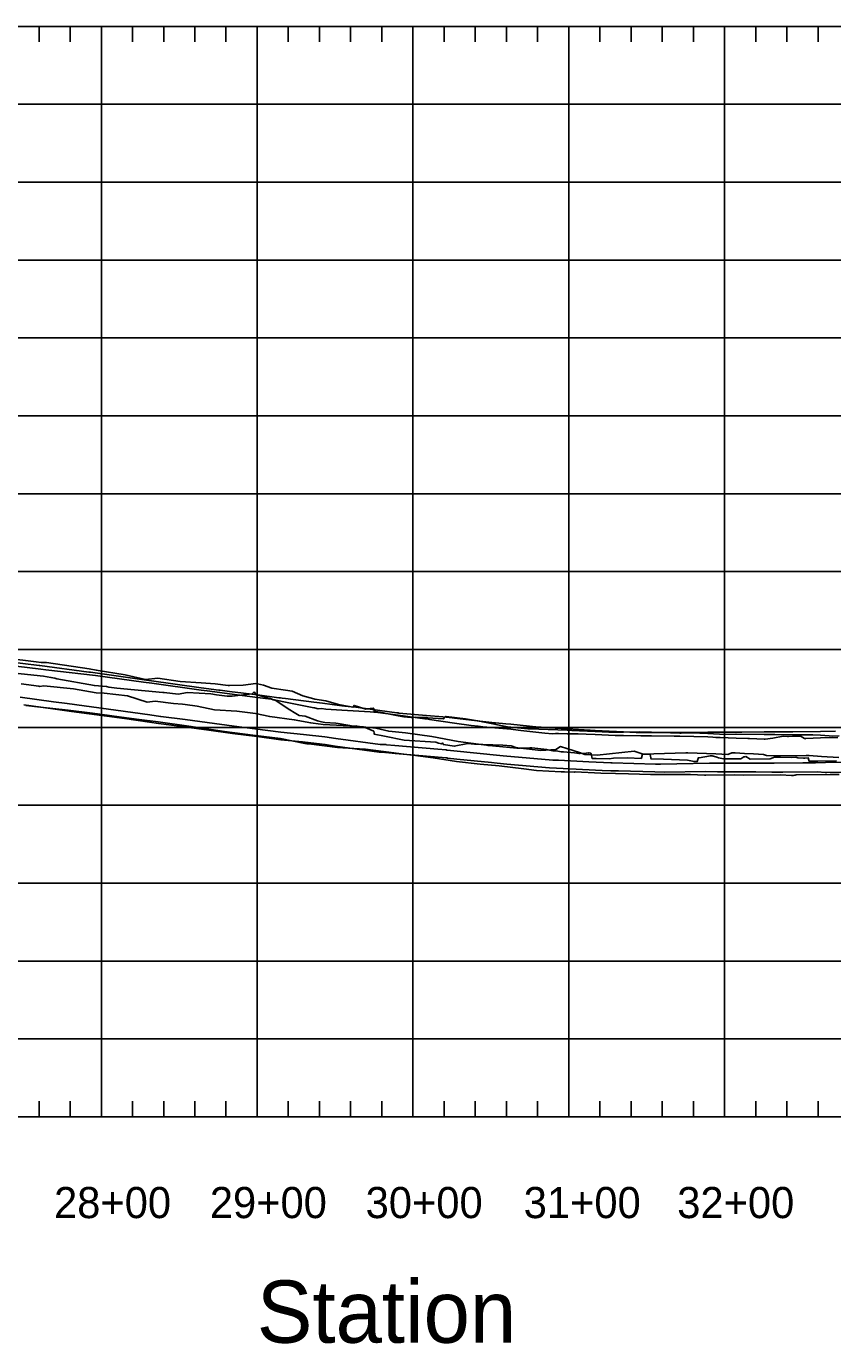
# Model space of a CAD drawing. Extents: x 704797 to 712284, y 374940 to 376945.
# Drawn here: x 709886 to 710403, y 375080 to 375925 of the extents above; entities that cross this region are included whole.
import ezdxf

# ---------------------------------------------------------------- set-up
doc = ezdxf.new("R2010")
doc.units = 0
for name, color, linetype in [('1', 7, 'Continuous'), ('10', 7, 'Continuous'), ('12', 7, 'Continuous'), ('13', 7, 'Continuous'), ('61', 7, 'Continuous'), ('63', 7, 'Continuous'), ('Existing', 7, 'Continuous')]:
    doc.layers.add(name, color=color, linetype=linetype)

msp = doc.modelspace()

# ---------------------------------------------------------------- linework, layer by layer
at = {"layer": '10'}
for points in [[(709874.16, 375510.77), (709896.6, 375508.33), (709901.33, 375507.58), (709903.88, 375507.11), (709905.03, 375506.66), (709929.22, 375502.35), (709936.92, 375501.68), (709938.59, 375501.37), (709943.57, 375500.56), (709973.07, 375497.79), (709973.91, 375497.97), (709983.05, 375496.9), (709988.96, 375497.86), (710003.85, 375496.96), (710007.55, 375496.38), (710014.44, 375495.56), (710017.75, 375495.62), (710030.51, 375497.11), (710031.58, 375498.13), (710031.88, 375498.04), (710033.05, 375496.4), (710042.27, 375494.03), (710043.98, 375493.21), (710045.71, 375492.68), (710053.54, 375487.38), (710058.53, 375484.49), (710060.7, 375483.2), (710064.53, 375482.76), (710072.32, 375479.69), (710074.96, 375479.06), (710077.22, 375478.54), (710084.29, 375478.21), (710085.63, 375477.99), (710096.72, 375476), (710096.96, 375476.45), (710099.86, 375475.54), (710101.93, 375475.8), (710108.48, 375473.03), (710108.73, 375471.73), (710108.84, 375471.09), (710115.47, 375469.77), (710128.15, 375467.26), (710148.28, 375465.93), (710150.14, 375465.42), (710151.19, 375465.11), (710152.13, 375464.82), (710152.17, 375464.81), (710152.19, 375464.8), (710152.44, 375465.2), (710152.63, 375465.48), (710153.07, 375464.65), (710153.23, 375464.48), (710160.24, 375463.33), (710168.93, 375465.17), (710173.26, 375464.68), (710178.44, 375464.42), (710191.28, 375464.14), (710196.68, 375463.55), (710200.34, 375462.34), (710200.95, 375462.27), (710215.7, 375460.59), (710225.37, 375461.34), (710228.32, 375463.16), (710240.54, 375459.32), (710243.97, 375457.99), (710252.02, 375457.64), (710275.68, 375460.31), (710275.75, 375460.31), (710281.54, 375458.28), (710308.82, 375459.2), (710309.49, 375459.18), (710310.05, 375459.15), (710328.09, 375458.41), (710335.69, 375458.07), (710338.46, 375459.16), (710340.4, 375459.07), (710346.55, 375458.77), (710352.36, 375458.45), (710358.7, 375458.06), (710360.67, 375457.53), (710366.75, 375457.18), (710369.64, 375457.29), (710386.12, 375457.39), (710388.07, 375457.4), (710395.99, 375456.88), (710407.07, 375456.25)], [(710405.48, 375454.11), (710393.53, 375453.9), (710387.88, 375453.9), (710387.78, 375454.52), (710387.39, 375455.88), (710385.27, 375455.82), (710384.33, 375455.8), (710380.67, 375455.94), (710379.41, 375456.35), (710376.94, 375456.18), (710369.27, 375456.28), (710365.85, 375456.3), (710362.98, 375455.38), (710350.07, 375455.14), (710347.39, 375456.69), (710346.72, 375456.68), (710346.14, 375456.48), (710344.2, 375455.3), (710342.88, 375455.32), (710339.01, 375455.33), (710333.06, 375455.23), (710329.76, 375455.99), (710328.76, 375456.26), (710326.63, 375456.91), (710326.31, 375456.99), (710325.65, 375457.15), (710325.06, 375457.24), (710324.57, 375457.24), (710320.99, 375456.54), (710317.49, 375455.99), (710316.83, 375455.94), (710316.71, 375455.54), (710316.21, 375453.57), (710314.08, 375453.65), (710309.92, 375454.39), (710294.54, 375455.13), (710286.53, 375455.26), (710286.37, 375455.58), (710286.3, 375456.03), (710285.88, 375458.04), (710284.62, 375458.22), (710283.8, 375458.33), (710282.8, 375458.38), (710280.92, 375458.26), (710280.44, 375456.01), (710280.36, 375455.7), (710280.29, 375455.56), (710271.24, 375455.93), (710262.47, 375455.76), (710259.7, 375455.36), (710251.18, 375455.5), (710248.91, 375455.53), (710248.7, 375455.55), (710248.47, 375456.63), (710248.02, 375458.27), (710247.81, 375458.89), (710247.59, 375458.96), (710246.88, 375459.06), (710246.59, 375459.04), (710246.1, 375459.03), (710245.28, 375459.04), (710245.15, 375459.03), (710241.07, 375458.63), (710240.06, 375458.82), (710238.78, 375459.02), (710237.3, 375459.18), (710230.42, 375459.76), (710228.74, 375459.86), (710225.64, 375460.36), (710223.43, 375460.49), (710221.28, 375460.92), (710219.71, 375461.28), (710209.95, 375462.33), (710209.27, 375462.4), (710209.11, 375462.41), (710208.95, 375462.43), (710208.8, 375462.44), (710202.45, 375462.07), (710201.93, 375462.09), (710201.44, 375462.1), (710200.99, 375462.11), (710200.6, 375462.11), (710200.28, 375462.1), (710182.36, 375463.89), (710181.65, 375463.92), (710181, 375463.96), (710175.83, 375464.73), (710162.71, 375466.49), (710145.79, 375469.59), (710128.92, 375472), (710118.17, 375473.02), (710109.92, 375474.88), (710106.03, 375475.39), (710105.67, 375475.41), (710097.45, 375476.18), (710076, 375477.41), (710069.73, 375478.27), (710068.07, 375478.33), (710057.47, 375480.39), (710041.74, 375482.39), (710032.52, 375484.33), (710020.7, 375485.8), (710006.38, 375486.83), (709995.09, 375489), (709987.53, 375490.13), (709985.74, 375490.38), (709979.96, 375490.9), (709968.24, 375492.24), (709963.15, 375491.74), (709950.42, 375495.66), (709935.39, 375497.4), (709930.34, 375497.76), (709915.87, 375500.13), (709896.72, 375502.14), (709893.91, 375501.82), (709893.55, 375501.86), (709882.12, 375503.53)]]:
    msp.add_lwpolyline(points, dxfattribs=at)
at = {"layer": '12'}
for points in [[(709881.53, 375494.85), (709902.9, 375491.88), (709911.68, 375490.71), (709953.84, 375485.03), (709964.73, 375483.49), (709971.71, 375482.48), (709971.77, 375482.48), (709987.44, 375480.47), (710001.6, 375478.55), (710018.85, 375476.22), (710032.1, 375474.56), (710048.94, 375472.42), (710063.49, 375470.91), (710077.06, 375469.39), (710084.16, 375468.33), (710112.69, 375464.59), (710116.04, 375464.4), (710116.39, 375464.48), (710116.72, 375464.34), (710121.97, 375463.77), (710149.67, 375461.43), (710155.02, 375461.1), (710155.43, 375460.96), (710155.66, 375460.9), (710159.83, 375460.49), (710189.41, 375457.51), (710191.56, 375457.3), (710223.57, 375454.54), (710224.55, 375454.51), (710227.02, 375454.38), (710246.66, 375453.42), (710260.61, 375452.72), (710261.48, 375452.69), (710289.38, 375451.86), (710292.65, 375451.86), (710324.11, 375452.41), (710328.95, 375452.44), (710359.12, 375452.57), (710365.63, 375452.6), (710383.96, 375452.74), (710392.02, 375452.8), (710398.39, 375452.87), (710414.32, 375453.15)], [(709884.02, 375489.91), (709901.14, 375487.53), (709914.44, 375485.76), (709948.6, 375481.14), (709964.61, 375478.88), (709970.34, 375478.06), (709983.55, 375476.32), (710002.7, 375473.68), (710017.77, 375471.6), (710033.65, 375469.56), (710048.88, 375467.57), (710062.69, 375466.1), (710077.24, 375464.43), (710083.85, 375463.42), (710112.1, 375459.61), (710115.64, 375459.41), (710116.03, 375459.5), (710116.38, 375459.34), (710122.25, 375458.69), (710147.6, 375456.5), (710154.89, 375456.04), (710155.47, 375455.84), (710155.8, 375455.75), (710161.95, 375455.13), (710184.06, 375452.85), (710187.74, 375452.48), (710193.97, 375451.87), (710221.23, 375449.53), (710225.91, 375449.37), (710255.07, 375447.88), (710260.62, 375447.64), (710265.56, 375447.66), (710288.91, 375446.97), (710295.11, 375446.8), (710321.45, 375447.23), (710329.06, 375446.89), (710348.29, 375446.91), (710353.73, 375446.93), (710364.09, 375446.84), (710371.02, 375446.77), (710393.45, 375446.87), (710398.34, 375446.53), (710399.3, 375446.46), (710412.7, 375446.66)]]:
    msp.add_lwpolyline(points, dxfattribs=at)
at = {"layer": '13'}
msp.add_lwpolyline([(710407.23, 375445.28), (710402.16, 375445.16), (710401.48, 375445.14), (710379.59, 375444.95), (710379.01, 375444.83), (710378.79, 375444.82), (710377.88, 375444.65), (710377.23, 375444.57), (710376.58, 375444.69), (710369.66, 375444.96), (710346.15, 375444.84), (710339.9, 375444.98), (710321.66, 375444.78), (710320.87, 375444.91), (710311.76, 375445.15), (710304.28, 375445.14), (710294.86, 375445.14), (710286.2, 375445.22), (710272, 375445.68), (710263.79, 375445.78), (710254.18, 375446.17), (710237.78, 375446.85), (710237.12, 375446.81), (710230.97, 375446.9), (710229.97, 375446.93), (710228.91, 375446.87), (710213.02, 375447.9), (710204.78, 375448.88), (710189.03, 375450.73), (710176.76, 375451.86), (710161.55, 375453.67), (710146.57, 375455.86), (710133.56, 375457.56), (710127.91, 375458.3), (710116.44, 375459.78), (710103.23, 375461.51), (710102.87, 375461.47), (710085.29, 375462.52), (710066.88, 375464.91), (710065.63, 375464.87), (710064.38, 375465.16), (710048.7, 375468.34), (710030.82, 375470.53), (710012.63, 375472.83), (709989.86, 375476.19), (709970.08, 375478.96), (709957.95, 375480.55), (709945.12, 375482.25), (709928.08, 375484.59), (709912.39, 375486.46), (709894.62, 375488.42), (709885.3, 375489.54)], dxfattribs=at)
at = {"layer": '61'}
for p, q in [((708133.69, 375925.47), (712133.69, 375925.47)), ((709893.69, 375925.47), (709893.69, 375915.47)), ((709913.69, 375925.47), (709913.69, 375915.47)), ((709933.69, 375225.47), (709933.69, 375925.47)), ((709953.69, 375925.47), (709953.69, 375915.47)), ((709973.69, 375925.47), (709973.69, 375915.47)), ((709993.69, 375925.47), (709993.69, 375915.47)), ((710013.69, 375925.47), (710013.69, 375915.47)), ((710033.69, 375225.47), (710033.69, 375925.47)), ((710053.69, 375925.47), (710053.69, 375915.47)), ((710073.69, 375925.47), (710073.69, 375915.47)), ((710093.69, 375925.47), (710093.69, 375915.47)), ((710113.69, 375925.47), (710113.69, 375915.47)), ((710133.69, 375225.47), (710133.69, 375925.47)), ((710153.69, 375925.47), (710153.69, 375915.47)), ((710173.69, 375925.47), (710173.69, 375915.47)), ((710193.69, 375925.47), (710193.69, 375915.47)), ((710213.69, 375925.47), (710213.69, 375915.47)), ((710233.69, 375225.47), (710233.69, 375925.47)), ((710253.69, 375925.47), (710253.69, 375915.47)), ((710273.69, 375925.47), (710273.69, 375915.47)), ((710293.69, 375925.47), (710293.69, 375915.47)), ((710313.69, 375925.47), (710313.69, 375915.47)), ((710333.69, 375225.47), (710333.69, 375925.47)), ((710353.69, 375925.47), (710353.69, 375915.47)), ((710373.69, 375925.47), (710373.69, 375915.47)), ((710393.69, 375925.47), (710393.69, 375915.47)), ((708133.69, 375875.47), (712133.69, 375875.47)), ((708133.69, 375825.47), (712133.69, 375825.47)), ((708133.69, 375775.47), (712133.69, 375775.47)), ((708133.69, 375725.47), (712133.69, 375725.47)), ((708133.69, 375675.47), (712133.69, 375675.47)), ((708133.69, 375625.47), (712133.69, 375625.47)), ((708133.69, 375575.47), (712133.69, 375575.47)), ((708133.69, 375525.47), (712133.69, 375525.47)), ((708133.69, 375475.47), (712133.69, 375475.47)), ((708133.69, 375425.47), (712133.69, 375425.47)), ((708133.69, 375375.47), (712133.69, 375375.47)), ((708133.69, 375325.47), (712133.69, 375325.47)), ((708133.69, 375275.47), (712133.69, 375275.47)), ((709893.69, 375225.47), (709893.69, 375235.47)), ((709913.69, 375225.47), (709913.69, 375235.47)), ((709953.69, 375225.47), (709953.69, 375235.47)), ((709973.69, 375225.47), (709973.69, 375235.47)), ((709993.69, 375225.47), (709993.69, 375235.47)), ((710013.69, 375225.47), (710013.69, 375235.47)), ((710053.69, 375225.47), (710053.69, 375235.47)), ((710073.69, 375225.47), (710073.69, 375235.47)), ((710093.69, 375225.47), (710093.69, 375235.47)), ((710113.69, 375225.47), (710113.69, 375235.47)), ((710153.69, 375225.47), (710153.69, 375235.47)), ((710173.69, 375225.47), (710173.69, 375235.47)), ((710193.69, 375225.47), (710193.69, 375235.47)), ((710213.69, 375225.47), (710213.69, 375235.47)), ((710253.69, 375225.47), (710253.69, 375235.47)), ((710273.69, 375225.47), (710273.69, 375235.47)), ((710293.69, 375225.47), (710293.69, 375235.47)), ((710313.69, 375225.47), (710313.69, 375235.47)), ((710353.69, 375225.47), (710353.69, 375235.47)), ((710373.69, 375225.47), (710373.69, 375235.47)), ((710393.69, 375225.47), (710393.69, 375235.47)), ((708133.69, 375225.47), (712133.69, 375225.47))]:
    msp.add_line(p, q, dxfattribs=at)
at = {"layer": '63'}
for points in [[(709845.14, 375518.75), (709893.22, 375513.02), (709894.82, 375512.83), (709898.1, 375512.47), (709929.91, 375508.75), (709960.84, 375504.58), (709966.08, 375503.9), (709997.78, 375499.47), (710001.52, 375498.95), (710006.52, 375498.21), (710015.85, 375497.04), (710033.92, 375494.76), (710039.12, 375494.1), (710042.65, 375493.67), (710051.98, 375491.77), (710070.05, 375488.1), (710070.51, 375488.01), (710072.75, 375487.48), (710075.01, 375487.54), (710077.85, 375487.17), (710088.12, 375486.55), (710106.19, 375485.44), (710108.56, 375485.3), (710108.62, 375485.31), (710111.06, 375484.98), (710124.25, 375483.26), (710141.25, 375481.04), (710142.32, 375480.9), (710144.4, 375480.63), (710160.39, 375478.29), (710171.09, 375476.73), (710175.6, 375476.19), (710178.46, 375475.93), (710196.52, 375474.26), (710198.05, 375474.12), (710202.98, 375473.53), (710214.59, 375472.16), (710218.33, 375471.71), (710223.22, 375471.39), (710225.18, 375471.51), (710227.04, 375471.45), (710232.66, 375471.36), (710238.49, 375471.27), (710239.75, 375471.34), (710244.83, 375471.12), (710250.73, 375470.88), (710263.44, 375470.34), (710268.79, 375470.28), (710279.96, 375470.14), (710283.55, 375470.02), (710286.86, 375469.99), (710301.37, 375469.84), (710304.9, 375469.83), (710304.93, 375469.83), (710323, 375469.32), (710326.17, 375469.23), (710328.13, 375468.92), (710330.93, 375468.94), (710341.06, 375468.66), (710348.6, 375468.44), (710349.61, 375468.44), (710359.13, 375468), (710359.7, 375467.97), (710364.72, 375468.6), (710371.36, 375469.74), (710374.19, 375469.66), (710374.39, 375469.66), (710374.54, 375469.66), (710374.67, 375469.67), (710377.2, 375469.74), (710379.11, 375469.79), (710382.65, 375469.61), (710382.81, 375469.62), (710385.09, 375468.3), (710385.14, 375468.23), (710385.74, 375468.37), (710385.82, 375468.42), (710395.27, 375468.69), (710406.5, 375469.02)], [(709872.78, 375519.96), (709891.75, 375517.5), (709895.11, 375517.06), (709898.41, 375517.2), (709925.9, 375512.96), (709930.46, 375512.3), (709949.03, 375509.11), (709962.05, 375506.26), (709970.02, 375507.07), (709984.18, 375505.02), (709997.78, 375504.13), (710006.75, 375503.53), (710015.12, 375502.26), (710015.85, 375502.28), (710024.81, 375502.54), (710032.77, 375503.57), (710033.92, 375503.33), (710037.76, 375502.49), (710043.04, 375500.69), (710051.98, 375499.34), (710056.11, 375498.7), (710063, 375495.75), (710070.05, 375493.86), (710070.76, 375493.67), (710077.87, 375492.46), (710085.98, 375490.21), (710088.12, 375489.81), (710095.28, 375488.47), (710095.88, 375489.62), (710103.35, 375487.23), (710106.19, 375487.57), (710108.08, 375487.79), (710108.31, 375487.83), (710108.46, 375487.67), (710108.54, 375487.51), (710108.86, 375485.8), (710109.98, 375485.62), (710114.59, 375484.83), (710124.25, 375482.92), (710127.91, 375482.19), (710132.58, 375481.88), (710133.59, 375481.92), (710135.4, 375481.94), (710138.59, 375481.89), (710142.32, 375481.75), (710143.24, 375481.71), (710153.14, 375480.92), (710153.23, 375481.04), (710153.38, 375481.04), (710154.04, 375481.85), (710154.64, 375482.51), (710154.79, 375482.36), (710154.92, 375482.34), (710155.07, 375482.38), (710160.39, 375481.78), (710167.33, 375481), (710175.19, 375479.7), (710178.46, 375479.04), (710178.46, 375479.03), (710194.46, 375475.77), (710196.52, 375475.57), (710207.36, 375474.52), (710208.19, 375474.45), (710214.59, 375474.24), (710232.66, 375473.64), (710233.19, 375473.63), (710235.69, 375473.5), (710250.73, 375472.84), (710259.47, 375472.46), (710268.79, 375472.51), (710279.16, 375472.56), (710284.7, 375472.39), (710286.86, 375472.33), (710304.93, 375471.81), (710305.9, 375471.78), (710312.75, 375471.9), (710323, 375471.46), (710334.03, 375470.99), (710340.89, 375471.02), (710341.06, 375471.02), (710359.13, 375470.88), (710366.04, 375470.84), (710377.2, 375470.74), (710382.11, 375470.7), (710390.3, 375470.76), (710395.27, 375470.44), (710400.74, 375470.08), (710402.77, 375469.93), (710407.34, 375470.02)]]:
    msp.add_lwpolyline(points, dxfattribs=at)
at = {"layer": 'Existing'}
msp.add_lwpolyline([(709862.15, 375518.98), (709893.78, 375515.16), (709894.2, 375515.11), (709925.69, 375510.96), (709926.69, 375510.83), (709964.12, 375505.58), (709964.17, 375505.57), (709964.3, 375505.56), (709997.78, 375500.97), (710009.19, 375499.42), (710009.96, 375499.31), (710015.85, 375498.56), (710033.92, 375496.28), (710047.64, 375494.55), (710048.19, 375494.48), (710048.67, 375494.42), (710049.73, 375494.31), (710051.98, 375494.02), (710070.05, 375491.71), (710075.57, 375491), (710088.12, 375489.37), (710094.08, 375488.6), (710095.06, 375488.47), (710095.21, 375488.6), (710095.56, 375488.58), (710106.19, 375487.14), (710123.31, 375484.81), (710124.25, 375484.73), (710124.53, 375484.71), (710142.32, 375483.14), (710152.76, 375482.22), (710155.03, 375482.02), (710155.1, 375482.01), (710158.85, 375481.59), (710160.39, 375481.41), (710178.46, 375479.36), (710186.25, 375478.47), (710186.75, 375478.42), (710193.22, 375477.81), (710196.52, 375477.48), (710214.59, 375475.69), (710215.91, 375475.55), (710217.13, 375475.47), (710232.66, 375474.51), (710247.13, 375473.61), (710247.35, 375473.6), (710250.73, 375473.45), (710268.79, 375472.66), (710277.01, 375472.3), (710277.85, 375472.27), (710286.86, 375472.28), (710304.93, 375472.28), (710311.13, 375472.27), (710312.3, 375472.27), (710323, 375472.35), (710341.06, 375472.48), (710343.63, 375472.5), (710344.8, 375472.51), (710359.13, 375472.58), (710376.78, 375472.65), (710377.2, 375472.65), (710377.55, 375472.65), (710395.27, 375472.86), (710404.92, 375472.97)], dxfattribs=at)

# ---------------------------------------------------------------- texts
at = {"layer": '1'}
msp.add_text('Station', height=40, dxfattribs=at).set_placement((710033.46, 375080.47))
at = {"layer": '61'}
for s, p in [('28+00', (709903.32, 375160.47)), ('29+00', (710003.32, 375160.47)), ('30+00', (710103.32, 375160.47)), ('31+00', (710204.77, 375160.47)), ('32+00', (710303.32, 375160.47))]:
    msp.add_text(s, height=20, dxfattribs=at).set_placement(p)

doc.saveas('drawing.dxf')
